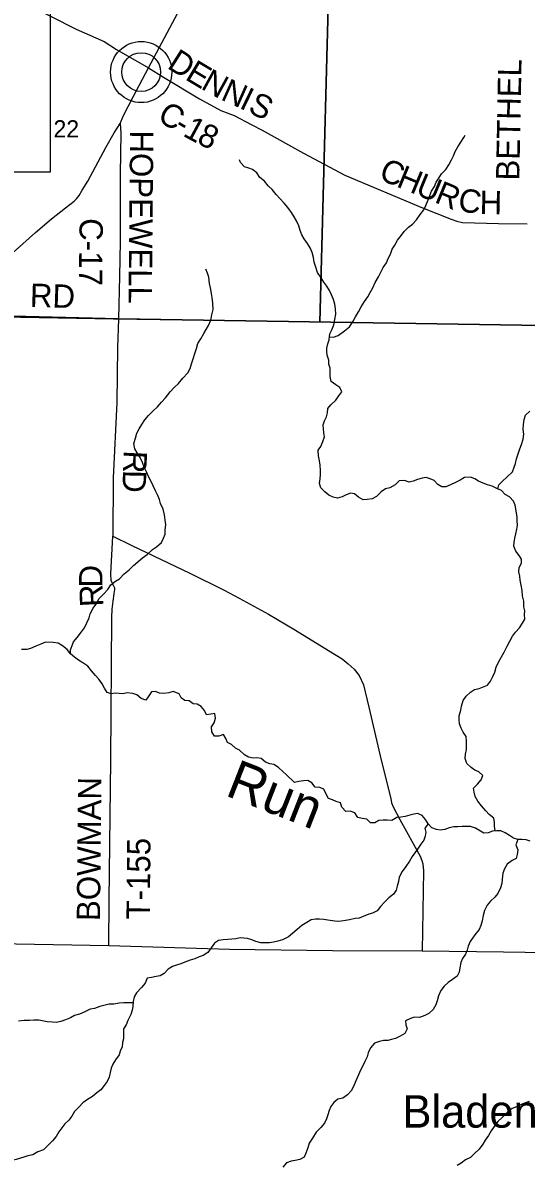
# Model space of a CAD drawing. Extents: x 1759416 to 2214760, y 252598 to 1116833.
# Drawn here: x 2019807 to 2026271, y 831751 to 846429 of the extents above; entities that cross this region are included whole.
import ezdxf

# ---------------------------------------------------------------- set-up
doc = ezdxf.new("R2010")
doc.units = 0
for name, color, linetype in [('GM_X_County_Road', 7, 'Continuous'), ('GM_X_County_Road_Text', 7, 'Continuous'), ('GM_X_Minor_River', 7, 'Continuous'), ('GM_X_Minor_River_Text', 7, 'Continuous'), ('GM_X_Section', 7, 'Continuous'), ('GM_X_Section_Text', 7, 'Continuous'), ('GM_X_Township', 7, 'Continuous'), ('GM_X_Township_Road', 7, 'Continuous'), ('GM_X_Township_Road_Text', 7, 'Continuous'), ('GM_X_Unincorporated', 7, 'Continuous'), ('GM_X_Unincorporated_Location', 7, 'Continuous'), ('GM_X_Unincorporated_Text', 7, 'Continuous'), ('GM_X_US_Route', 7, 'Continuous'), ('SC_Scratch1', 7, 'Continuous')]:
    doc.layers.add(name, color=color, linetype=linetype)

msp = doc.modelspace()

# ---------------------------------------------------------------- linework, layer by layer
at = {"layer": 'GM_X_County_Road'}
for points in [[(2010910, 851435), (2011842, 851218), (2012814, 850978), (2013166, 850907), (2013198, 850897), (2013234, 850871), (2013350, 850774), (2014026, 850233), (2014399, 849950), (2014932, 849538), (2015428, 849142), (2015793, 848887), (2016839, 848202), (2017215, 847993), (2018403, 847379), (2018779, 847184), (2019841, 846677), (2020493, 846349), (2020853, 846191), (2021009, 846088), (2021420, 845852)], [(2021420, 845852), (2021612, 845733), (2022077, 845451), (2022350, 845305), (2022519, 845240), (2022749, 845117), (2022882, 845049), (2023410, 844754), (2023943, 844470), (2024939, 844053), (2025306, 843907), (2025380, 843880), (2025454, 843862), (2025915, 843849), (2026285, 843845)], [(2021057, 845135), (2021065, 845011), (2021059, 844490), (2021055, 843615), (2021047, 843176), (2021034, 842626)], [(2018481, 842691), (2021034, 842626)], [(2021034, 842626), (2021024, 842256), (2021012, 841553), (2020969, 840585), (2020963, 839833), (2021208, 839715), (2021951, 839356), (2022391, 839139), (2022585, 839038), (2022964, 838831), (2023309, 838626), (2023733, 838365), (2023910, 838256), (2023986, 838193), (2024062, 838125), (2024127, 838042), (2024183, 837922), (2024249, 837634), (2024410, 836954), (2024531, 836463), (2024543, 836409), (2024563, 836357), (2024648, 836192), (2024908, 835721), (2024932, 835667), (2024946, 835625), (2024953, 835532), (2024937, 834504), (2025982, 834493), (2026820, 834478)], [(2010634, 834765), (2011771, 834756), (2012697, 834721), (2013567, 834695), (2014258, 834672), (2014657, 834674), (2015288, 834665), (2015449, 834670), (2015551, 834675), (2015617, 834712), (2015691, 834732), (2015760, 834739), (2016048, 834732), (2016755, 834710), (2019479, 834600), (2020911, 834572), (2022462, 834527), (2023784, 834508), (2024937, 834504)]]:
    msp.add_lwpolyline(points, dxfattribs=at)
at = {"layer": 'GM_X_Minor_River'}
for points in [[(2023744, 842393), (2023796, 842391), (2023858, 842413), (2023940, 842470), (2024004, 842524), (2024050, 842598), (2024081, 842652), (2024117, 842714), (2024151, 842781), (2024193, 842849), (2024237, 842909), (2024269, 842965), (2024301, 843025), (2024331, 843092), (2024373, 843164), (2024409, 843234), (2024435, 843286), (2024477, 843345), (2024499, 843401), (2024527, 843457), (2024551, 843521), (2024585, 843573), (2024618, 843635), (2024670, 843700), (2024706, 843750), (2024758, 843804), (2024812, 843844), (2024864, 843900), (2024908, 843967), (2024958, 844025), (2024982, 844083), (2025012, 844157), (2025032, 844209), (2025054, 844266), (2025092, 844328), (2025116, 844382), (2025150, 844432), (2025182, 844488), (2025238, 844545), (2025277, 844605), (2025311, 844667), (2025339, 844719), (2025361, 844775), (2025393, 844834), (2025431, 844896), (2025471, 844958), (2025489, 844988)], [(2023713, 842249), (2023722, 842305), (2023742, 842357), (2023748, 842433), (2023774, 842486), (2023799, 842550), (2023815, 842618), (2023825, 842688), (2023821, 842756), (2023813, 842816), (2023795, 842875), (2023773, 842935), (2023745, 842989), (2023709, 843045), (2023671, 843099), (2023638, 843153), (2023592, 843223), (2023568, 843290), (2023550, 843354), (2023538, 843412), (2023522, 843478), (2023496, 843538), (2023462, 843592), (2023418, 843655), (2023392, 843707), (2023369, 843763), (2023351, 843819), (2023323, 843885), (2023293, 843935), (2023257, 843993), (2023211, 844057), (2023163, 844112), (2023109, 844172), (2023059, 844222), (2023010, 844288), (2022958, 844336), (2022910, 844396), (2022850, 844442), (2022814, 844502), (2022758, 844544), (2022708, 844562), (2022654, 844578), (2022604, 844633), (2022588, 844671)], [(2020420, 838323), (2020421, 838373), (2020441, 838427), (2020457, 838477), (2020505, 838532), (2020561, 838602), (2020597, 838656), (2020627, 838718), (2020657, 838786), (2020673, 838837), (2020709, 838909), (2020757, 838973), (2020785, 839029), (2020841, 839087), (2020897, 839150), (2020937, 839206), (2020995, 839254), (2021048, 839284), (2021110, 839348), (2021172, 839401), (2021228, 839455), (2021344, 839555), (2021402, 839597), (2021472, 839662), (2021524, 839696), (2021588, 839750), (2021612, 839806), (2021634, 839860), (2021634, 839910), (2021644, 839983), (2021636, 840041), (2021628, 840107), (2021610, 840179), (2021575, 840253), (2021563, 840305), (2021541, 840358), (2021509, 840416), (2021481, 840478), (2021451, 840546), (2021419, 840600), (2021393, 840660), (2021367, 840722), (2021342, 840781), (2021312, 840843), (2021276, 840905), (2021246, 840955), (2021234, 841023), (2021252, 841093), (2021272, 841156), (2021300, 841212), (2021336, 841268), (2021374, 841328), (2021422, 841386), (2021480, 841445), (2021538, 841497), (2021586, 841555), (2021637, 841609), (2021697, 841686), (2021751, 841744), (2021807, 841796), (2021863, 841864), (2021925, 841932), (2021955, 841989), (2021971, 842049), (2021993, 842111), (2022017, 842181), (2022037, 842245), (2022055, 842308), (2022093, 842368), (2022133, 842438), (2022163, 842488), (2022190, 842540), (2022222, 842611), (2022236, 842677), (2022250, 842745), (2022246, 842827), (2022240, 842899), (2022232, 842952), (2022218, 843024), (2022206, 843082), (2022196, 843162), (2022177, 843214), (2022155, 843264), (2022159, 843256)], [(2024767, 840529), (2024707, 840547), (2024639, 840543), (2024587, 840495), (2024521, 840454), (2024463, 840440), (2024409, 840402), (2024351, 840342), (2024293, 840314), (2024231, 840304), (2024179, 840300), (2024117, 840334), (2024067, 840378), (2024015, 840384), (2023961, 840366), (2023909, 840340), (2023847, 840321), (2023791, 840333), (2023737, 840361), (2023686, 840404), (2023636, 840454), (2023616, 840510), (2023626, 840572), (2023628, 840624), (2023628, 840678), (2023624, 840744), (2023618, 840801), (2023606, 840865), (2023598, 840937), (2023634, 840987), (2023658, 841051), (2023679, 841108), (2023673, 841162), (2023667, 841212), (2023663, 841262), (2023679, 841314), (2023705, 841366), (2023719, 841420), (2023725, 841473), (2023763, 841523), (2023827, 841579), (2023867, 841635), (2023903, 841689), (2023879, 841743), (2023827, 841776), (2023766, 841822), (2023752, 841886), (2023756, 841942), (2023752, 841994), (2023738, 842044), (2023736, 842096), (2023716, 842157), (2023712, 842207), (2023713, 842249)], [(2025906, 840440), (2025922, 840492), (2025966, 840542), (2026024, 840592), (2026096, 840660), (2026119, 840718), (2026135, 840769), (2026149, 840825), (2026169, 840891), (2026189, 840955), (2026213, 841013), (2026233, 841078), (2026241, 841146), (2026233, 841208), (2026237, 841268), (2026245, 841334), (2026261, 841390), (2026317, 841441)], [(2025874, 836046), (2025866, 836105), (2025866, 836155), (2025854, 836208), (2025794, 836256), (2025754, 836306), (2025697, 836368), (2025651, 836428), (2025615, 836490), (2025603, 836542), (2025595, 836594), (2025647, 836647), (2025691, 836703), (2025715, 836757), (2025663, 836805), (2025613, 836827), (2025563, 836863), (2025511, 836913), (2025488, 836977), (2025492, 837034), (2025504, 837094), (2025506, 837144), (2025504, 837200), (2025500, 837258), (2025462, 837314), (2025438, 837366), (2025414, 837421), (2025410, 837475), (2025412, 837525), (2025431, 837597), (2025441, 837649), (2025463, 837723), (2025501, 837778), (2025555, 837830), (2025609, 837862), (2025669, 837874), (2025773, 837918), (2025815, 837972), (2025843, 838029), (2025867, 838085), (2025885, 838149), (2025921, 838221), (2025955, 838283), (2025987, 838344), (2026025, 838420), (2026061, 838484), (2026095, 838548), (2026132, 838598), (2026186, 838657), (2026224, 838715), (2026252, 838767), (2026250, 838825), (2026256, 838875), (2026242, 838927), (2026240, 838998), (2026224, 839068), (2026218, 839134), (2026206, 839204), (2026194, 839266), (2026190, 839319), (2026175, 839375), (2026179, 839431), (2026211, 839485), (2026211, 839537), (2026179, 839587), (2026139, 839639), (2026111, 839704), (2026115, 839754), (2026125, 839806), (2026137, 839862), (2026151, 839922), (2026159, 839976), (2026156, 840029), (2026156, 840079), (2026144, 840161), (2026128, 840231), (2026110, 840281), (2026058, 840337), (2026002, 840367), (2025956, 840419), (2025894, 840445), (2025834, 840474), (2025776, 840492), (2025720, 840514), (2025661, 840538), (2025611, 840570), (2025555, 840592), (2025477, 840588), (2025423, 840555), (2025365, 840525), (2025301, 840491), (2025239, 840469), (2025189, 840467), (2025137, 840499), (2025091, 840549), (2025037, 840571), (2024985, 840589), (2024935, 840577), (2024877, 840563), (2024821, 840539), (2024767, 840529)], [(2020420, 838323), (2020377, 838379), (2020315, 838423), (2020261, 838459), (2020195, 838467), (2020097, 838473), (2020039, 838447), (2019973, 838421), (2019907, 838389), (2019857, 838377), (2019789, 838375)], [(2025284, 836085), (2025226, 836063), (2025168, 836057), (2025118, 836063), (2025061, 836085), (2025013, 836139), (2024979, 836193), (2024935, 836243), (2024881, 836269), (2024829, 836263), (2024779, 836249), (2024717, 836233), (2024663, 836223), (2024611, 836217), (2024545, 836180), (2024487, 836184), (2024435, 836186), (2024381, 836178), (2024327, 836150), (2024273, 836148), (2024223, 836196), (2024163, 836204), (2024111, 836220), (2024071, 836278), (2024011, 836298), (2023957, 836296), (2023902, 836350), (2023886, 836408), (2023832, 836422), (2023782, 836444), (2023732, 836462), (2023698, 836525), (2023674, 836581), (2023620, 836603), (2023560, 836609), (2023518, 836663), (2023468, 836695), (2023410, 836691), (2023352, 836683), (2023296, 836669), (2023195, 836765), (2023145, 836809), (2023091, 836863), (2023029, 836899), (2022977, 836909), (2022923, 836931), (2022867, 836975), (2022813, 836983), (2022763, 836979), (2022705, 836993), (2022655, 837023), (2022589, 837083), (2022537, 837109), (2022486, 837155), (2022436, 837183), (2022412, 837234), (2022382, 837284), (2022324, 837264), (2022268, 837262), (2022234, 837318), (2022232, 837384), (2022262, 837434), (2022280, 837494), (2022272, 837554), (2022222, 837548), (2022166, 837538), (2022142, 837594), (2022098, 837646), (2022045, 837674), (2021995, 837680), (2021945, 837717), (2021889, 837723), (2021839, 837755), (2021815, 837807), (2021739, 837837), (2021683, 837821), (2021619, 837811), (2021561, 837818), (2021509, 837836), (2021459, 837832), (2021425, 837780), (2021385, 837728), (2021327, 837748), (2021273, 837794), (2021221, 837812), (2021147, 837820), (2021093, 837806), (2021043, 837812), (2020991, 837818), (2020941, 837808), (2020889, 837826), (2020854, 837882), (2020824, 837934), (2020784, 837994), (2020740, 838044), (2020690, 838105), (2020640, 838161), (2020578, 838207), (2020520, 838239), (2020470, 838277), (2020420, 838323)], [(2025013, 836139), (2024971, 836082), (2024981, 836032), (2024974, 835980), (2024958, 835928), (2024918, 835874), (2024874, 835810), (2024808, 835719), (2024774, 835657), (2024726, 835587), (2024680, 835523), (2024642, 835450), (2024630, 835396), (2024614, 835336), (2024600, 835284), (2024568, 835234), (2024508, 835186), (2024456, 835133), (2024401, 835073), (2024357, 835017), (2024299, 834991), (2024249, 834977), (2024179, 834945), (2024127, 834925), (2024075, 834920), (2024001, 834904), (2023951, 834896), (2023897, 834886), (2023843, 834880), (2023784, 834890), (2023724, 834900), (2023672, 834906), (2023616, 834912), (2023566, 834912), (2023508, 834902), (2023454, 834870), (2023390, 834830), (2023332, 834778), (2023276, 834731), (2023220, 834687), (2023140, 834647), (2023080, 834629), (2023028, 834615), (2022976, 834607), (2022926, 834609), (2022862, 834607), (2022798, 834623), (2022748, 834645), (2022692, 834665), (2022600, 834671), (2022542, 834661), (2022490, 834654), (2022438, 834650), (2022380, 834648), (2022320, 834640), (2022268, 834604), (2022184, 834484), (2022124, 834446), (2022070, 834430), (2022016, 834403), (2021958, 834385), (2021888, 834359), (2021834, 834339), (2021782, 834323), (2021730, 834305), (2021674, 834269), (2021624, 834213), (2021572, 834186), (2021520, 834174), (2021458, 834162), (2021402, 834152), (2021376, 834088), (2021332, 834034), (2021268, 833966), (2021237, 833913), (2021223, 833853), (2021221, 833791), (2021211, 833741), (2021195, 833685), (2021157, 833609), (2021135, 833554), (2021101, 833502), (2021099, 833440), (2021101, 833376), (2021089, 833326), (2021081, 833272), (2021058, 833217), (2021042, 833167), (2020998, 833105), (2020964, 833051), (2020942, 832997), (2020930, 832943), (2020916, 832882), (2020892, 832826), (2020852, 832774), (2020808, 832718), (2020756, 832682), (2020702, 832634), (2020638, 832595), (2020576, 832551), (2020526, 832495)], [(2026324, 835915), (2026270, 835931), (2026216, 835935), (2026166, 835935), (2026110, 835953), (2026056, 835987), (2026000, 836023), (2025946, 836045), (2025896, 836049), (2025840, 836041), (2025784, 836021), (2025728, 836017), (2025620, 836081), (2025558, 836103), (2025500, 836101), (2025448, 836103), (2025394, 836097), (2025340, 836097), (2025284, 836085)], [(2026166, 835935), (2026140, 835869), (2026165, 835805), (2026155, 835744), (2026143, 835690), (2026091, 835664), (2026025, 835618), (2025993, 835558), (2025973, 835502), (2025963, 835425), (2025957, 835371), (2025943, 835313), (2025907, 835243), (2025867, 835193), (2025813, 835145), (2025769, 835092), (2025737, 835024), (2025719, 834958), (2025704, 834890), (2025688, 834832), (2025668, 834779), (2025612, 834709), (2025550, 834625), (2025528, 834567), (2025514, 834515), (2025494, 834462), (2025454, 834408), (2025430, 834356), (2025418, 834286), (2025412, 834232), (2025384, 834178), (2025326, 834135), (2025270, 834099), (2025217, 834051), (2025177, 833995), (2025145, 833925), (2025129, 833864), (2025113, 833810), (2025075, 833750), (2025023, 833700), (2024971, 833676), (2024903, 833650), (2024839, 833652), (2024785, 833636), (2024723, 833605), (2024725, 833555), (2024741, 833503), (2024713, 833443), (2024651, 833407), (2024593, 833379), (2024543, 833365), (2024493, 833353), (2024437, 833352), (2024387, 833340), (2024323, 833320), (2024273, 833260), (2024241, 833194), (2024229, 833142), (2024197, 833082), (2024173, 833027), (2024145, 832973), (2024118, 832911), (2024082, 832835), (2024052, 832763), (2024022, 832706), (2023978, 832654), (2023916, 832612), (2023854, 832598), (2023802, 832558), (2023762, 832504), (2023740, 832453), (2023724, 832397), (2023706, 832345), (2023680, 832289), (2023636, 832233), (2023574, 832173), (2023526, 832098), (2023483, 832034), (2023469, 831972), (2023443, 831904), (2023419, 831854), (2023365, 831823), (2023303, 831811), (2023251, 831803), (2023195, 831779), (2023145, 831725)], [(2021222, 833836), (2021159, 833839), (2021105, 833837), (2021045, 833833), (2020977, 833819), (2020915, 833821), (2020795, 833791), (2020727, 833763), (2020672, 833757), (2020605, 833722), (2020535, 833692), (2020469, 833676), (2020417, 833644), (2020355, 833620), (2020293, 833598), (2020237, 833584), (2020186, 833588), (2020120, 833592), (2020012, 833616), (2019948, 833614), (2019892, 833612), (2019822, 833611), (2019750, 833603)], [(2026311, 832570), (2026251, 832546), (2026199, 832526), (2026147, 832502), (2026093, 832479), (2026037, 832437), (2025965, 832369), (2025907, 832313), (2025860, 832249), (2025822, 832192), (2025786, 832132), (2025746, 832072), (2025716, 832022), (2025666, 831956), (2025606, 831899), (2025554, 831851), (2025492, 831821), (2025436, 831777), (2025384, 831747)], [(2020526, 832495), (2020470, 832441), (2020436, 832381), (2020397, 832330), (2020345, 832282), (2020309, 832232), (2020269, 832178), (2020233, 832120), (2020189, 832062), (2020131, 832009), (2020071, 831947), (2019999, 831921), (2019935, 831883), (2019873, 831869), (2019821, 831853), (2019721, 831825), (2019669, 831810), (2019619, 831802), (2019563, 831788), (2019501, 831772), (2019431, 831756), (2019371, 831738)]]:
    msp.add_lwpolyline(points, dxfattribs=at)
at = {"layer": 'GM_X_Section'}
for points in [[(2023761, 847932), (2023623, 842584), (2023064, 842590), (2020970, 842622), (2018344, 842669), (2018441, 848066), (2021074, 848052)], [(2028982, 847785), (2028939, 842497), (2025052, 842562), (2023623, 842584), (2023761, 847932)]]:
    msp.add_lwpolyline(points, close=True, dxfattribs=at)
at = {"layer": 'GM_X_Township'}
for points in [[(2029345, 867783), (2029128, 855177), (2029103, 853671), (2029053, 849934), (2029030, 849879), (2029030, 849829), (2029046, 849735), (2029046, 849495), (2029029, 848523), (2029018, 847875), (2028952, 842930), (2028943, 842500), (2021034, 842626), (2018481, 842691), (2018354, 842694), (2015674, 842761), (2014123, 842824), (2010315, 842932)], [(2010315, 842932), (2014123, 842824), (2015674, 842761), (2018354, 842694), (2018481, 842691), (2021034, 842626), (2028943, 842500), (2028942, 842357), (2028902, 839762), (2028867, 837251), (2028838, 834843), (2028833, 833954), (2028816, 833356), (2028805, 832839), (2028798, 832529), (2028803, 832220), (2028809, 831909), (2028807, 831533)]]:
    msp.add_lwpolyline(points, dxfattribs=at)
at = {"layer": 'GM_X_Township_Road'}
msp.add_lwpolyline([(2020911, 834572), (2020916, 835150), (2020935, 836955), (2020951, 838788), (2020956, 838896), (2020966, 838998), (2020979, 839091), (2020985, 839127), (2020988, 839145), (2020987, 839165), (2020979, 839183), (2020955, 839235), (2020942, 839263), (2020938, 839351), (2020963, 839833)], dxfattribs=at)
at = {"layer": 'GM_X_Unincorporated'}
for radius in [393, 249]:
    msp.add_circle((2021327, 845797), radius, dxfattribs=at)
at = {"layer": 'GM_X_Unincorporated_Location'}
msp.add_line((2021327, 845797), (2021327, 845797), dxfattribs=at)
at = {"layer": 'GM_X_US_Route'}
msp.add_lwpolyline([(2019520, 843331), (2019971, 843737), (2020173, 843910), (2020353, 844051), (2020465, 844138), (2020497, 844168), (2020531, 844212), (2020571, 844279), (2020642, 844395), (2020873, 844827), (2020982, 845018), (2021057, 845135), (2021095, 845229), (2021224, 845479), (2021420, 845852), (2022068, 847069)], dxfattribs=at)
at = {"layer": 'SC_Scratch1'}
msp.add_lwpolyline([(1984253, 880416), (2020157, 880416), (2020157, 844512), (1984253, 844512)], close=True, dxfattribs=at)

# ---------------------------------------------------------------- texts
at = {"layer": 'GM_X_County_Road_Text'}
for s, rotation, p in [('D', 327.6467, (2021648, 845855)), ('E', 329.003, (2021878, 845709)), ('N', 331.0697, (2022081, 845588)), ('N', 335.8588, (2022336, 845448)), ('I', 334.189, (2022575, 845341)), ('S', 333.5136, (2022685, 845288)), ('C', 328.5295, (2021519, 845183)), ('1', 331.5616, (2021850, 844983)), ('HOPEWELL', 269.4929, (2021184, 845048)), ('-', 329.5293, (2021734, 845051)), ('8', 334.5244, (2022028, 844887)), ('C', 337.5369, (2024365, 844424)), ('H', 337.5382, (2024592, 844330)), ('U', 337.5441, (2024836, 844229)), ('R', 337.6249, (2025081, 844128)), ('C', 351.557, (2025385, 844013)), ('H', 358.9434, (2025671, 843973)), ('C-17', 269.3245, (2020536, 843921)), ('RD', 358.1851, (2019894, 842781)), ('R', 267.3021, (2021105, 840939)), ('D', 268.7941, (2021093, 840685))]:
    msp.add_text(s, height=300, rotation=rotation, dxfattribs=at).set_placement(p)
at = {"layer": 'GM_X_Minor_River_Text'}
msp.add_text('Run', height=500, rotation=338.6304, dxfattribs=at).set_placement((2022391, 836507))
at = {"layer": 'GM_X_Section_Text'}
msp.add_text('22', height=221, rotation=0, dxfattribs=at).set_placement((2020201, 844957))
at = {"layer": 'GM_X_Township_Road_Text'}
for s, rotation, p in [('BETHEL', 88.9224, (2026183, 844401)), ('D', 90.4517, (2020830, 839175)), ('R', 92.9716, (2020843, 838932)), ('BOWMAN', 89.4106, (2020798, 834887)), ('T-155', 89.4386, (2021437, 834907))]:
    msp.add_text(s, height=300, rotation=rotation, dxfattribs=at).set_placement(p)
at = {"layer": 'GM_X_Unincorporated_Text'}
msp.add_text('Bladensburg', height=417, rotation=0, dxfattribs=at).set_placement((2024683, 832233))

doc.saveas('drawing.dxf')
